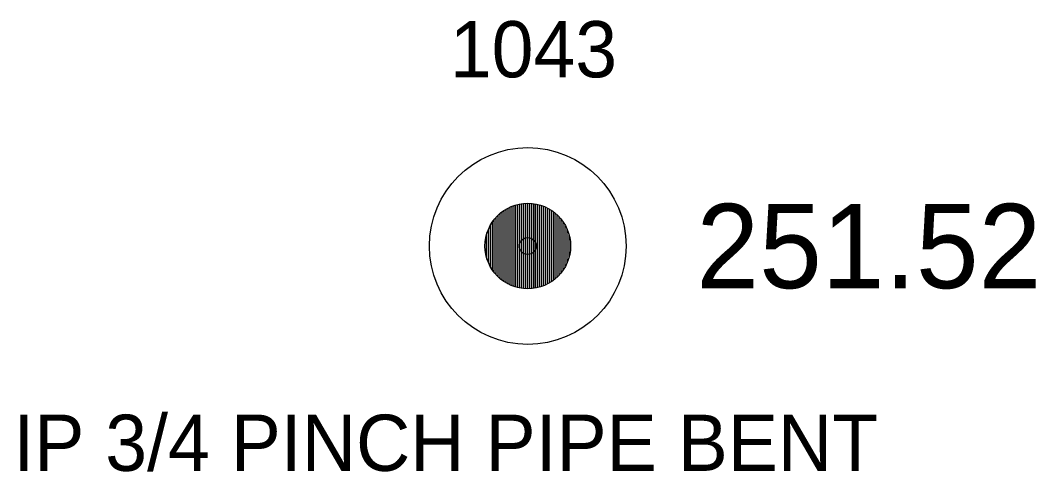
# Model space of a CAD drawing. Extents: x 1961231 to 1962574, y 799865 to 801120.
# Drawn here: x 1961355.41 to 1961373.47, y 800755.52 to 800763.55 of the extents above; entities that cross this region are included whole.
import ezdxf

# ---------------------------------------------------------------- set-up
doc = ezdxf.new("R2010")
doc.units = 0
for name, color, linetype in [('RD_EX_DV_Prop_txCode', 7, 'Continuous'), ('RD_EX_DV_PropPin', 7, 'Continuous'), ('RD_EX_TX_DV_Prop_ELEV', 7, 'Continuous'), ('RD_SMD_Locator', 7, 'Continuous')]:
    doc.layers.add(name, color=color, linetype=linetype)

msp = doc.modelspace()

# ---------------------------------------------------------------- linework, layer by layer
at = {"layer": 'RD_EX_DV_PropPin'}
for p, q in [((1961363.985, 800758.922), (1961363.985, 800760.142)), ((1961364.02, 800758.897), (1961364.02, 800760.166)), ((1961364.055, 800758.875), (1961364.055, 800760.188)), ((1961364.09, 800758.856), (1961364.09, 800760.207)), ((1961364.125, 800758.839), (1961364.125, 800760.225)), ((1961364.16, 800758.824), (1961364.16, 800760.239)), ((1961364.195, 800758.811), (1961364.195, 800760.252)), ((1961364.23, 800758.8), (1961364.23, 800760.263)), ((1961364.265, 800758.791), (1961364.265, 800760.272)), ((1961364.3, 800758.784), (1961364.3, 800760.28)), ((1961364.335, 800758.778), (1961364.335, 800760.286)), ((1961364.37, 800758.774), (1961364.37, 800760.29)), ((1961364.405, 800758.772), (1961364.405, 800760.292)), ((1961364.44, 800758.771), (1961364.44, 800760.293)), ((1961364.475, 800758.772), (1961364.475, 800760.292)), ((1961364.51, 800758.774), (1961364.51, 800760.29)), ((1961364.545, 800758.778), (1961364.545, 800760.286)), ((1961364.58, 800758.784), (1961364.58, 800760.28)), ((1961364.615, 800758.791), (1961364.615, 800760.272)), ((1961364.65, 800758.8), (1961364.65, 800760.263)), ((1961364.685, 800758.811), (1961364.685, 800760.252)), ((1961364.72, 800758.824), (1961364.72, 800760.239)), ((1961364.755, 800758.839), (1961364.755, 800760.225)), ((1961364.79, 800758.856), (1961364.79, 800760.207)), ((1961364.825, 800758.875), (1961364.825, 800760.188)), ((1961364.86, 800758.897), (1961364.86, 800760.166)), ((1961364.895, 800758.922), (1961364.895, 800760.142)), ((1961363.81, 800759.105), (1961363.81, 800759.958)), ((1961363.845, 800759.058), (1961363.845, 800760.006)), ((1961363.88, 800759.017), (1961363.88, 800760.047)), ((1961363.915, 800758.981), (1961363.915, 800760.083)), ((1961363.95, 800758.95), (1961363.95, 800760.114)), ((1961364.93, 800758.95), (1961364.93, 800760.114)), ((1961364.965, 800758.981), (1961364.965, 800760.083)), ((1961365, 800759.017), (1961365, 800760.047)), ((1961365.035, 800759.058), (1961365.035, 800760.006)), ((1961365.07, 800759.105), (1961365.07, 800759.958)), ((1961363.74, 800759.234), (1961363.74, 800759.83)), ((1961363.775, 800759.162), (1961363.775, 800759.901)), ((1961365.105, 800759.162), (1961365.105, 800759.901)), ((1961365.14, 800759.234), (1961365.14, 800759.83)), ((1961363.705, 800759.336), (1961363.705, 800759.728)), ((1961365.175, 800759.336), (1961365.175, 800759.728))]:
    msp.add_line(p, q, dxfattribs=at)
for radius in [1.75, 0.761]:
    msp.add_circle((1961364.44, 800759.532), radius, dxfattribs=at)
at = {"layer": 'RD_SMD_Locator'}
msp.add_circle((1961364.44, 800759.532), 0.15, dxfattribs=at)

# ---------------------------------------------------------------- texts
at = {"layer": 'RD_EX_DV_Prop_txCode'}
for s, p in [('1043', (1961363.054, 800762.532)), ('IP 3/4 PINCH PIPE BENT', (1961355.29, 800755.532))]:
    msp.add_text(s, height=1, dxfattribs=at).set_placement(p)
at = {"layer": 'RD_EX_TX_DV_Prop_ELEV'}
msp.add_text('251.52', height=1.5, dxfattribs=at).set_placement((1961367.44, 800758.782))

doc.saveas('drawing.dxf')
